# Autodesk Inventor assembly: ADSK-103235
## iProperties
Shininess: 0.0
Created: 2000-09
Part Number: ADSK-103235
Document SubType Name: Assembly
Designer: gao
Stock Number: ADSK-103235
Density: 0.0
Volumn: 0.0
Area: 0.0
PropertySet Name: Model Information
Control State: 0
Master: False
Checked Out: False
Author: gao
